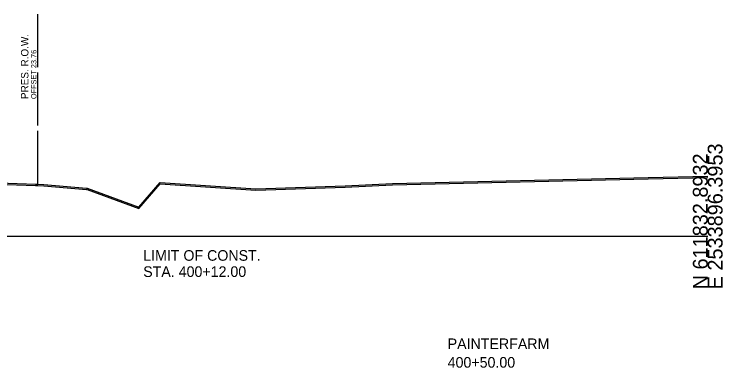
# Model space of a CAD drawing. Extents: x -26 to 453, y 80 to 2034.
# Drawn here: x 143.7 to 277.2, y 475.2 to 541.8 of the extents above; entities that cross this region are included whole.
import ezdxf

# ---------------------------------------------------------------- set-up
doc = ezdxf.new("R2010")
doc.units = 0
for name, color, linetype in [('DESIGN - SHEET - Light Grid', 7, 'Continuous'), ('DESIGN - TRANSPORTATION - Text', 7, 'Continuous'), ('DESIGN - TYPICAL - Warning Text', 7, 'Continuous'), ('SURVEY - GROUND - Bottom of Topsoil Layer', 7, 'Continuous'), ('SURVEY - GROUND - Top of Ground', 7, 'Continuous'), ('SURVEY - PROPERTY - ROW Lines', 7, 'Continuous'), ('SURVEY - PROPERTY - ROW Lines Text', 7, 'Continuous')]:
    doc.layers.add(name, color=color, linetype=linetype)

msp = doc.modelspace()

# ---------------------------------------------------------------- linework, layer by layer
at = {"layer": 'DESIGN - SHEET - Light Grid'}
msp.add_line((124.32, 500), (274.32, 500), dxfattribs=at)
at = {"layer": 'SURVEY - GROUND - Bottom of Topsoil Layer'}
for p, q in [((214.94, 509.67), (263.09, 510.85)), ((263.09, 510.85), (274.32, 511.07)), ((135.63, 509.99), (147.7, 509.59)), ((147.7, 509.59), (148.12, 509.59)), ((148.12, 509.59), (149.26, 509.49)), ((149.26, 509.49), (157.29, 508.83)), ((157.29, 508.83), (157.43, 508.83)), ((157.43, 508.83), (167.11, 505.23)), ((167.11, 505.23), (171.16, 509.88)), ((171.16, 509.88), (189.18, 508.71)), ((189.18, 508.71), (206.04, 509.26)), ((206.04, 509.26), (214.94, 509.67))]:
    msp.add_line(p, q, dxfattribs=at)
at = {"layer": 'SURVEY - GROUND - Top of Ground'}
msp.add_lwpolyline([(135.63, 510.24), (147.7, 509.84), (148.12, 509.84), (149.26, 509.74), (157.29, 509.08), (157.43, 509.08), (167.11, 505.48), (171.16, 510.13), (189.18, 508.96), (206.04, 509.51), (214.94, 509.92), (263.09, 511.1), (274.32, 511.32)], dxfattribs=at)
at = {"layer": 'SURVEY - PROPERTY - ROW Lines'}
for p, q in [((148.09, 531.84), (148.09, 541.84)), ((148.09, 520.84), (148.09, 530.84)), ((148.09, 509.84), (148.09, 519.84))]:
    msp.add_line(p, q, dxfattribs=at)

# ---------------------------------------------------------------- texts
at = {"layer": 'DESIGN - SHEET - Light Grid'}
for s, p in [('E 2533896.3953', (277.12, 490)), ('N 611832.8932', (274.32, 490))]:
    msp.add_text(s, height=2.8, rotation=90, dxfattribs=at).set_placement(p)
at = {"layer": 'DESIGN - TRANSPORTATION - Text'}
for s, p in [('LIMIT OF CONST.', (167.96, 495.39)), ('STA. 400+12.00', (167.96, 492.34))]:
    msp.add_text(s, height=2, dxfattribs=at).set_placement(p)
at = {"layer": 'DESIGN - TYPICAL - Warning Text'}
for s, p in [('PAINTERFARM', (225.32, 478.75)), ('400+50.00', (225.32, 475.25))]:
    msp.add_text(s, height=2, dxfattribs=at).set_placement(p)
at = {"layer": 'SURVEY - PROPERTY - ROW Lines Text'}
for s, height, p in [('PRES. R.O.W.', 1.4, (146.34, 525.84)), ('OFFSET 23.76', 1, (147.84, 525.84))]:
    msp.add_text(s, height=height, rotation=90, dxfattribs=at).set_placement(p)

doc.saveas('drawing.dxf')
